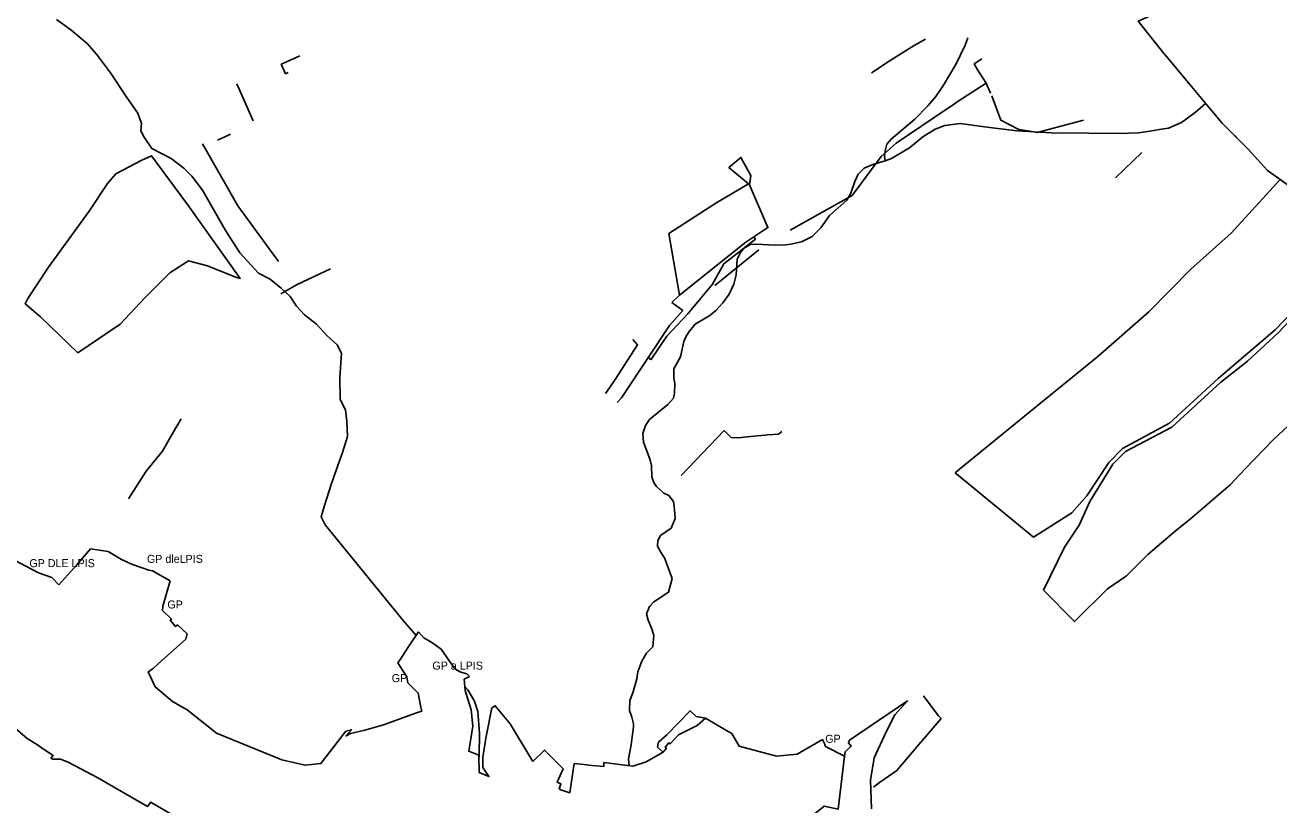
# Model space of a CAD drawing. Extents: x -617038 to -609441, y -1109294 to -1104285.
# Drawn here: x -612071 to -610504, y -1108263 to -1107289 of the extents above; entities that cross this region are included whole.
import ezdxf

# ---------------------------------------------------------------- set-up
doc = ezdxf.new("R2010")
doc.units = 0
for name, color, linetype in [('BOD_SET', 7, 'Continuous'), ('GRA_ZV', 7, 'Continuous'), ('LES_ZV', 7, 'Continuous'), ('Level 255', 7, 'Continuous'), ('OVNE_PRE', 7, 'Continuous'), ('OVNE_SET', 7, 'Continuous'), ('OVNI_SET', 7, 'Continuous'), ('VODA', 7, 'Continuous')]:
    doc.layers.add(name, color=color, linetype=linetype)

msp = doc.modelspace()

# ---------------------------------------------------------------- linework, layer by layer
at = {"layer": 'BOD_SET'}
for p, q in [((-610646.8, -1107325.9), (-610645.8, -1107326.9)), ((-610646.8, -1107326.9), (-610645.8, -1107325.9)), ((-610618, -1107360.6), (-610617, -1107361.6)), ((-610618, -1107361.6), (-610617, -1107360.6)), ((-610558.8, -1107427.7), (-610557.8, -1107428.7)), ((-610558.8, -1107428.7), (-610557.8, -1107427.7))]:
    msp.add_line(p, q, dxfattribs=at)
at = {"layer": 'GRA_ZV'}
for points in [[(-611991, -1107521.8), (-611967.9, -1107487.1), (-611957.4, -1107474.8), (-611924.8, -1107458.1), (-611913.1, -1107452.5), (-611867.9, -1107513.5), (-611802.2, -1107605.9), (-611806.7, -1107604.7), (-611842.9, -1107589.8), (-611866.8, -1107583.6), (-611890.1, -1107598.7), (-611921.3, -1107629.9), (-611952, -1107662.9), (-612005.1, -1107698.5), (-612051.6, -1107653.8), (-612070.8, -1107637.2), (-612067.4, -1107630.8), (-612041.5, -1107591.4), (-611991, -1107521.8)], [(-611266.6, -1107549.6), (-611207.8, -1107511.8), (-611166.8, -1107487.6), (-611191.3, -1107467.3), (-611176.4, -1107454.4), (-611164, -1107476.9), (-611165.6, -1107488.8), (-611142.5, -1107542.2), (-611170.3, -1107560.5), (-611252.9, -1107626.5), (-611266.6, -1107549.6)], [(-610908.7, -1107848.4), (-610907.8, -1107847.8), (-610822.1, -1107777.9), (-610730.3, -1107703.1), (-610666.7, -1107647.5), (-610613.9, -1107593.9), (-610563.6, -1107549.3), (-610502.3, -1107482.1)], [(-610473.2, -1107633.1), (-610508.5, -1107669.8), (-610579.7, -1107730.8), (-610640.9, -1107786.3), (-610699.6, -1107818.2), (-610716.6, -1107835.5), (-610744, -1107877.1), (-610762.7, -1107898.3), (-610810.8, -1107928.8), (-610908.7, -1107848.4)], [(-610798.3, -1107995), (-610771.9, -1107941.4), (-610753.6, -1107914), (-610740.2, -1107884.2), (-610711.4, -1107837.8), (-610695.7, -1107821.7), (-610638, -1107791.5), (-610576.5, -1107735.4), (-610543.4, -1107709), (-610504.8, -1107673.6), (-610468.5, -1107635.2)], [(-610480.3, -1107778.4), (-610510.6, -1107806.9), (-610546.1, -1107843.7), (-610565, -1107863.4), (-610614.4, -1107905.9)], [(-610614.4, -1107905.9), (-610633.8, -1107921.2), (-610668, -1107950.6), (-610694.5, -1107977.2), (-610718.2, -1107993.2), (-610759.5, -1108034.2), (-610798.3, -1107995)], [(-611046, -1108197.1), (-611038.4, -1108190), (-611041.9, -1108185.9), (-611040.6, -1108182.4), (-610968, -1108133.4), (-610983.8, -1108150.7), (-610994.5, -1108171), (-611009.9, -1108204.6), (-611014.5, -1108232.5), (-611014.1, -1108244.1), (-611013.1, -1108268.3)], [(-611054.6, -1108268.6), (-611047, -1108202.2), (-611046, -1108197.1)]]:
    msp.add_lwpolyline(points, dxfattribs=at)
at = {"layer": 'LES_ZV'}
for p, q in [((-611785.7, -1107408.6), (-611806.2, -1107362.4)), ((-610919.3, -1107394.4), (-610912.4, -1107389.5)), ((-611037.2, -1107501.9), (-611001.1, -1107453.4)), ((-610675.3, -1107448.4), (-610708.4, -1107479.9)), ((-611114.6, -1107545.4), (-611037.2, -1107501.9)), ((-611208.9, -1107614.4), (-611154, -1107570)), ((-611288.9, -1107707.2), (-611291.8, -1107703.9)), ((-611197.1, -1107795.6), (-611250.8, -1107852))]:
    msp.add_line(p, q, dxfattribs=at)
for points in [[(-610945.7, -1107306.6), (-610959.8, -1107314.5), (-610989.8, -1107333.5), (-611013.1, -1107348.9)], [(-611750.7, -1107338.2), (-611745, -1107335.6), (-611727.4, -1107327.7)], [(-610869.9, -1107361.9), (-610881.1, -1107344.3), (-610884.7, -1107337.5), (-610875.3, -1107331.5)], [(-611750.7, -1107338.2), (-611745.4, -1107350), (-611742, -1107348.5)], [(-610864.5, -1107374.4), (-610869.9, -1107361.9), (-610904.9, -1107384.2), (-610912.4, -1107389.5)], [(-610862.8, -1107377.4), (-610851.7, -1107408), (-610829.1, -1107419.5), (-610815.2, -1107421.9), (-610806.3, -1107423.5), (-610748.1, -1107408)], [(-611001.1, -1107453.4), (-610982.2, -1107436.9), (-610919.3, -1107394.4)], [(-611830.5, -1107432.8), (-611821.3, -1107428.7), (-611814.2, -1107425.5)], [(-611849.3, -1107437.6), (-611805.2, -1107515), (-611754.1, -1107584.7)], [(-611160.3, -1107553.9), (-611158.3, -1107556.5), (-611197.7, -1107587.4), (-611211.9, -1107612.8), (-611242.7, -1107650), (-611269, -1107677.8), (-611288.9, -1107707.2)], [(-611262.7, -1107635.9), (-611252.9, -1107626.5), (-611170.3, -1107560.5), (-611160.3, -1107553.9)], [(-611751.3, -1107624.7), (-611730.7, -1107613.2), (-611689.4, -1107593.7)], [(-611291.8, -1107703.9), (-611265.5, -1107664.3), (-611249.1, -1107645.7), (-611262.7, -1107635.9)], [(-611311.2, -1107681.9), (-611305.4, -1107688.5), (-611333.5, -1107732), (-611340.4, -1107742.3), (-611345.6, -1107749.6)], [(-611331, -1107760.5), (-611325.7, -1107754.8), (-611291.8, -1107703.9)], [(-611941.7, -1107881), (-611919.5, -1107846.6), (-611899.2, -1107821.3), (-611885.2, -1107797.4), (-611875.9, -1107781.2)], [(-611125.3, -1107797), (-611129.2, -1107800), (-611143.2, -1107801.1), (-611145.5, -1107801.3), (-611156, -1107802.1), (-611180.2, -1107804.7), (-611188.3, -1107804.5), (-611197.1, -1107795.6)], [(-610925.9, -1108155.3), (-610930, -1108151.8), (-610948.2, -1108126.9)], [(-611273.6, -1108197.2), (-611280.7, -1108191), (-611279.2, -1108185), (-611268.9, -1108175.9), (-611239.8, -1108145.7), (-611232.1, -1108153), (-611220.6, -1108154.8)], [(-611010.5, -1108241.2), (-611003.3, -1108235.4), (-610981.3, -1108220.5), (-610951.3, -1108185.1), (-610950.5, -1108184.1), (-610925.9, -1108155.3)]]:
    msp.add_lwpolyline(points, dxfattribs=at)
at = {"layer": 'OVNE_PRE'}
for points in [[(-610574.7, -1107411.6), (-610598.8, -1107383.5), (-610617.5, -1107361.1), (-610646.3, -1107326.4), (-610647.2, -1107325.3), (-610679.7, -1107284.3), (-610642.7, -1107268), (-610613, -1107258.5)], [(-610493.5, -1107488.4), (-610502.3, -1107482.1), (-610518.3, -1107470.7), (-610542.6, -1107444), (-610558.3, -1107428.2), (-610574.7, -1107411.6)]]:
    msp.add_lwpolyline(points, dxfattribs=at)
at = {"layer": 'OVNI_SET'}
for p, q in [((-611911.5, -1107971), (-611889.5, -1107983.4)), ((-611515.4, -1108102.9), (-611522.1, -1108106.3))]:
    msp.add_line(p, q, dxfattribs=at)
for points in [[(-612028.6, -1107988.2), (-612006.3, -1107963.3), (-611989, -1107943.4)], [(-611989, -1107943.4), (-611967.1, -1107946.9), (-611950.4, -1107956.9), (-611936.6, -1107962.8), (-611925.8, -1107966.8), (-611916.3, -1107970.2), (-611911.5, -1107971)], [(-612115.8, -1107992.1), (-612084.1, -1107957.4), (-612054.1, -1107973.6), (-612037.6, -1107979.3), (-612028.6, -1107988.2)], [(-611889.5, -1107983.4), (-611898.6, -1108015), (-611899.2, -1108020.6), (-611887.8, -1108031.4), (-611889.4, -1108032.7), (-611882.8, -1108040.6), (-611880.3, -1108038.5), (-611868.5, -1108049.6), (-611870.2, -1108056.3), (-611904.5, -1108087.2), (-611910.8, -1108092.9), (-611916.9, -1108097.2), (-611908.3, -1108115.7), (-611886.7, -1108134.2), (-611868.3, -1108144.4), (-611831.7, -1108173.6), (-611749.9, -1108206.9), (-611721, -1108213.7), (-611701.2, -1108211.5), (-611669.9, -1108171.2), (-611663.1, -1108169.5), (-611669.8, -1108177.1), (-611664.2, -1108173.9), (-611646.3, -1108169.8), (-611623.1, -1108163.2), (-611580.5, -1108147.9), (-611575.2, -1108146.1), (-611576.2, -1108141.3), (-611579.6, -1108123.7), (-611592.5, -1108110.8), (-611593.8, -1108103.4)], [(-611602.2, -1108081.6), (-611599.6, -1108077.8), (-611591.2, -1108065.1), (-611579.3, -1108047.1)], [(-611579.3, -1108047.1), (-611572.7, -1108054.4), (-611562.5, -1108060.5), (-611551, -1108068.8), (-611548, -1108072.9), (-611533.8, -1108093.2), (-611526.4, -1108097.6), (-611518.9, -1108099.4), (-611515.4, -1108102.9)], [(-611593.8, -1108103.4), (-611605.2, -1108085.8), (-611602.2, -1108081.6)], [(-611522.1, -1108106.3), (-611520.9, -1108120.2), (-611513.6, -1108144.7), (-611511.2, -1108164.9)], [(-612128.2, -1108126.6), (-612118.2, -1108134.8), (-612112.2, -1108139.7), (-612102.3, -1108150.3), (-612098.2, -1108154.6), (-612068.2, -1108180.2), (-612054.2, -1108189.1), (-612050.2, -1108192.1), (-612035.8, -1108201.5), (-612038.6, -1108204.8), (-612036.4, -1108206.3), (-612026.5, -1108206.3), (-612017.1, -1108209.8)], [(-611503.4, -1108222.8), (-611491.3, -1108227.9), (-611498.7, -1108216.5), (-611498.9, -1108203.9), (-611494.9, -1108179.9), (-611494.2, -1108175.6), (-611487.8, -1108142.1), (-611483.3, -1108139.5), (-611464.7, -1108162.2), (-611436.3, -1108209.1)], [(-611511.2, -1108164.9), (-611516.5, -1108196.2), (-611503.9, -1108201.2), (-611503.4, -1108222.8)], [(-611347.5, -1108210.3), (-611311.5, -1108214.8), (-611294.6, -1108209.5), (-611273.6, -1108197.2), (-611269.4, -1108192.5), (-611271, -1108191.1), (-611266.4, -1108185.9), (-611264.8, -1108187.2), (-611254.5, -1108175.6), (-611231.1, -1108164), (-611220.6, -1108154.8)], [(-611025.9, -1108358.5), (-611049.8, -1108343.5), (-611054.5, -1108340.8), (-611068.4, -1108326.1), (-611077.6, -1108318.3), (-611079.2, -1108317), (-611084.1, -1108312.9), (-611092.4, -1108307.2), (-611109.8, -1108295.5), (-611106.4, -1108292.3), (-611072.1, -1108264.7), (-611054.6, -1108268.6), (-611047, -1108202.2), (-611070.5, -1108190.5), (-611071.8, -1108186.4), (-611074.4, -1108181.6), (-611106.1, -1108200), (-611131.8, -1108202.4), (-611178.6, -1108190.1), (-611187.6, -1108174.1), (-611192.3, -1108171.4), (-611220.6, -1108154.8)], [(-611436.3, -1108209.1), (-611421.9, -1108194.9), (-611398.6, -1108218.1), (-611406, -1108234.9), (-611401.3, -1108236.9), (-611403.6, -1108243.1), (-611401.4, -1108244.3)], [(-612017.1, -1108209.8), (-611980, -1108229.3), (-611918, -1108265.2), (-611913.7, -1108259.8), (-611910.3, -1108261.8), (-611856.8, -1108293.1)], [(-611401.4, -1108244.3), (-611390.3, -1108248.2), (-611384.5, -1108211.6), (-611368.3, -1108213.3), (-611366.6, -1108213.5), (-611347.8, -1108215.5), (-611347.5, -1108210.3)]]:
    msp.add_lwpolyline(points, dxfattribs=at)
at = {"layer": 'VODA'}
for points in [[(-611582.3, -1108051.7), (-611590.5, -1108042.3), (-611598.6, -1108032.9), (-611695.8, -1107913.6), (-611700.9, -1107903.4), (-611696.6, -1107889.4), (-611688.5, -1107863.2), (-611682.6, -1107846.6), (-611674.1, -1107822.9), (-611667.9, -1107803.2), (-611668.9, -1107784.2), (-611670.6, -1107769.7), (-611677, -1107757), (-611677.6, -1107729.9), (-611675.5, -1107699), (-611681, -1107688.4), (-611693.7, -1107676.9), (-611706.6, -1107662.6), (-611721.7, -1107651), (-611731.5, -1107640.4), (-611739.8, -1107628.4), (-611751, -1107617.8), (-611764.8, -1107606.5), (-611779.2, -1107599.2), (-611802.4, -1107573.5), (-611820.9, -1107544.9), (-611849.3, -1107495.6), (-611862.3, -1107477.9), (-611872.4, -1107467.8), (-611888.4, -1107455.8), (-611912.5, -1107443.4), (-611922.1, -1107429), (-611926.2, -1107421.3), (-611925.3, -1107412.2), (-611930, -1107399.3), (-611943.6, -1107379.6), (-611964.1, -1107348.7), (-611981.7, -1107325.5), (-611993.3, -1107312.4), (-612013.7, -1107295.2), (-612031.8, -1107282.1)], [(-610996.2, -1107458.6), (-610996.7, -1107452.8), (-610996.1, -1107446.1), (-610993.8, -1107437.8), (-610988.7, -1107431.7), (-610959.1, -1107406.8), (-610942.8, -1107390.2), (-610932.9, -1107378.4), (-610923.2, -1107364.4), (-610907.2, -1107337.6), (-610896.1, -1107314.3), (-610892.6, -1107305)], [(-611271.3, -1107955.3), (-611276, -1107948.5), (-611280.7, -1107940.1), (-611280.3, -1107932.9), (-611276.9, -1107926.9), (-611263.5, -1107917.4), (-611258.4, -1107905.5), (-611259.3, -1107894.9), (-611260.7, -1107884.3), (-611266.3, -1107876.9), (-611272.6, -1107873.9), (-611281.9, -1107865.5), (-611284.8, -1107861.2), (-611287.5, -1107853.9), (-611288, -1107839.4), (-611289.6, -1107832.1), (-611298, -1107810.3), (-611299, -1107799.5), (-611295.5, -1107789.4), (-611290.6, -1107781.9), (-611267.6, -1107763.1), (-611260.6, -1107755.4), (-611259.4, -1107748.9), (-611258.7, -1107737.2), (-611260.2, -1107729.9), (-611260.1, -1107718.6), (-611251.8, -1107703.6), (-611247.6, -1107684.3), (-611245.2, -1107678.6), (-611242, -1107673.1), (-611233.6, -1107662.8), (-611215.1, -1107652.1), (-611207.6, -1107645.6), (-611199, -1107636), (-611191.2, -1107625.5), (-611185.1, -1107613), (-611182.3, -1107601.2), (-611180.9, -1107581.6), (-611176.8, -1107573.2), (-611170.9, -1107566.9), (-611164.5, -1107563.3), (-611156.8, -1107562.9), (-611134.3, -1107564), (-611120.8, -1107563.8), (-611114.1, -1107563), (-611100.7, -1107559.8), (-611087.4, -1107553.1), (-611076.3, -1107542.4), (-611065.7, -1107526.9), (-611044, -1107507.9), (-611038.8, -1107499.3), (-611034.1, -1107484.6), (-611030, -1107475.4), (-611022.3, -1107468.1), (-611011.4, -1107463.2), (-610996.2, -1107458.6), (-610988.2, -1107455.7), (-610965.6, -1107442.7), (-610949, -1107428.8), (-610933.6, -1107419.3), (-610921.3, -1107414.8), (-610902.3, -1107412), (-610872, -1107416.5), (-610831.7, -1107421.3), (-610788.1, -1107423.8), (-610694.3, -1107424.5), (-610691.8, -1107424.4), (-610678.9, -1107423.9), (-610660.5, -1107421), (-610650.6, -1107419.4), (-610642.1, -1107418.1), (-610625.6, -1107410.9), (-610608.6, -1107398.6), (-610595.6, -1107387)], [(-611315.8, -1108214.4), (-611316.9, -1108205.7), (-611313.4, -1108188.1), (-611312.2, -1108178.3), (-611310.4, -1108166.2), (-611310.6, -1108162), (-611312.5, -1108153.6), (-611315.7, -1108145.3), (-611315.1, -1108133), (-611311.2, -1108123.5), (-611306.2, -1108106), (-611305.1, -1108097.1), (-611300.3, -1108083.6), (-611294.1, -1108073.6), (-611286.5, -1108065.8), (-611285.2, -1108051.8), (-611287.6, -1108043.5), (-611292.2, -1108032.5), (-611294.1, -1108024.6), (-611290.4, -1108015.3), (-611285.1, -1108009.8), (-611266.9, -1107997.7), (-611262.2, -1107980.3), (-611269.2, -1107961.5), (-611271.3, -1107955.3)], [(-611503.8, -1108206.6), (-611503.5, -1108201), (-611503, -1108173.9), (-611505.1, -1108146.5), (-611509.1, -1108133.8), (-611517.6, -1108119.4), (-611521.4, -1108115.4)]]:
    msp.add_lwpolyline(points, dxfattribs=at)

# ---------------------------------------------------------------- texts
at = {"layer": 'Level 255'}
msp.add_text('GP a LPIS', height=10, dxfattribs=at).set_placement((-611561.9, -1108094.3))
at = {"layer": 'OVNE_SET'}
for s, p in [('GP DLE LPIS', (-612065.5, -1107966.3)), ('GP dleLPIS', (-611918.6, -1107961)), ('GP', (-611893.1, -1108017.9)), ('GP', (-611612.7, -1108109.9)), ('GP', (-611070.9, -1108185.7))]:
    msp.add_text(s, height=10, dxfattribs=at).set_placement(p)

doc.saveas('drawing.dxf')
